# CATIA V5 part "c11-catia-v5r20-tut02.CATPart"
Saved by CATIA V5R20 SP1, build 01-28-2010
Part number: c11tut2
Bounding box of the stored display mesh (mm): x -175 to 0, y -36.667 to 105, z 0 to 36.632
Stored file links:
  D:\v5_r20\psrt_files_downloaded\c11\c11-catia-v5r20-tut02.CATPart
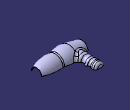
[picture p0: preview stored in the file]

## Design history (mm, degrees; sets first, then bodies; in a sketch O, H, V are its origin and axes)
Body1 (main body)
  Plane1: type Offset, RefPlane yz-plane, Offset 75, reversed
  Plane2: type Offset, RefPlane yz-plane, Offset 125, reversed
  Plane3: type Offset, RefPlane yz-plane, Offset 175, reversed
  Sketch1 on yz-plane, origin (0, 0, 0), H (0, 1, 0), V (0, 0, 1)
    arc A1 centre (0, 0) radius 20 from (20, 0) to (-20, 0) ccw
    point P1 (-20, 0)
    point P2 (20, 0)
    radius A1 = 20
    coincidence: P1 H, P2 H
  Sketch2 on Plane1, origin (-75, 0, 0), H (0, 1, 0), V (0, 0, 1)
    arc A1 centre (0, 0) radius 30 from (30, 0) to (-30, 0) ccw
    point P1 (-30, 0)
    point P2 (30, 0)
    radius A1 = 30
    coincidence: P1 H, P2 H
  Sketch3 on Plane2, origin (-125, 0, 0), H (0, 1, 0), V (0, 0, 1)
    arc A1 centre (0, 0) radius 35 from (35, 0) to (-35, 0) ccw
    point P1 (-35, 0)
    point P2 (35, 0)
    radius A1 = 35
    coincidence: P1 H, P2 H
  Sketch4 on Plane3, origin (-175, 0, 0), H (0, 1, 0), V (0, 0, 1)
    arc A1 centre (0, 0) radius 25 from (25, 0) to (-25, 0) ccw
    point P1 (-25, 0)
    point P2 (25, 0)
    radius A1 = 25
    coincidence: P1 H, P2 H
  Sketch5 on xy-plane, origin (0, 0, 0), H (1, 0, 0), V (0, 1, 0)
    arc A1 centre (-53.2457, -93.0924) radius 125 from (0, 20) to (-75, 30) ccw
    point P2 (0, 20)
    point P3 (-75, 30)
    reference projected point E1 (0, 20) from Sketch1.P2
    reference projected point E2 (-75, 30) from Sketch2.P2
    line L1 (-175, 25) -> (-125, 35)
    point P4 (-175, 25)
    point P5 (-125, 35)
    reference projected point E3 (-125, 35) from Sketch3.P2
    reference projected point E4 (-175, 25) from Sketch4.P2
    arc A2 centre (-108.1667, -49.1667) radius 85.8335 from (-75, 30) to (-125, 35) ccw
    radius A1 = 125
    coincidence: P2 V, P2 E1, P3 E2, P5 E3, E4 P4
    tangency: A2 L1
  Sketch6 on xy-plane, origin (0, 0, 0), H (1, 0, 0), V (0, 1, 0)
    reference projected line E1 (-125, 35) -> (-175, 25) from Sketch5.L1
    point P1 (-125, 35)
    point P2 (-175, 25)
    reference projected arc E2 centre (-108.1667, -49.1667) radius 85.8335 from (-75, 30) to (-125, 35) ccw from Sketch5.A2
    point P3 (-75, 30)
    point P4 (-125, 35)
    reference projected arc E3 centre (-53.2457, -93.0924) radius 125 from (0, 20) to (-75, 30) ccw from Sketch5.A1
    point P5 (0, 20)
    point P6 (-75, 30)
    point P7 (-75, -30)
    point P8 (0, -20)
    point P9 (-125, -35)
    point P10 (-75, -30)
    point P11 (-175, -25)
    point P12 (-125, -35)
    arc A1 centre (-53.2457, 93.0924) radius 125 from (0, -20) to (-75, -30) cw
    arc A2 centre (-108.1667, 49.1667) radius 85.8335 from (-75, -30) to (-125, -35) cw
    line L1 (-125, -35) -> (-175, -25)
    symmetry: P6 P7 H, P5 P8 H, E3 A1 H, P4 P9 H, P3 P10 H, E2 A2 H, P2 P11 H, P1 P12 H, E1 L1 H
  Loft1: Sections (Sketch1; Sketch2; Sketch3; Sketch4), Guides (Sketch5; Sketch6)
  Sketch7 on xy-plane, origin (0, 0, 0), H (1, 0, 0), V (0, 1, 0)
    line L1 (-160, 10) -> (-160, 105)
    point P1 (-160, 10)
    point P2 (-160, 105)
    reference projected line E1 (-175, -25) -> (-175, 25) from edge of Loft1
    reference projected point E2 (-175, 25) from vertex [face of Loft1]
    distance P1 E1 = 15
    distance E2 P1 V = 15
    distance H P2 = 105
    vertical: L1 V
  Sketch8 on xy-plane, origin (0, 0, 0), H (1, 0, 0), V (0, 1, 0)
    point P1 (-125, 105)
    construction line L1 (-125, 105) -> (-110.3491, 0.7536)
    line L2 (-125, 105) -> (-123.011, 90.8478)
    point P3 (-123.011, 90.8478)
    arc A1 centre (-129.9429, 89.8736) radius 7 from (-125.3895, 84.5571) to (-123.011, 90.8478) ccw
    point P5 (-123.011, 90.8478)
    arc A2 centre (-121.4865, 80) radius 6 from (-125.3895, 84.5571) to (-123.3627, 74.3009) ccw
    point P7 (-121.4865, 80)
    arc A3 centre (-124.8481, 69.7891) radius 4.75 from (-122.6028, 65.6033) to (-123.3627, 74.3009) ccw
    arc A4 centre (-118.3485, 57.6723) radius 9 from (-122.6028, 65.6033) to (-122.4134, 49.6426) ccw
    point P11 (-118.3485, 57.6723)
    arc A5 centre (-127.8333, 38.9362) radius 12 from (-115.9501, 40.6063) to (-122.4134, 49.6426) ccw
    construction line L3 (-160, 10) -> (-111.6486, 10)
    point P15 (-160, 10)
    line L4 (-111.6486, 10) -> (-115.9501, 40.6063)
    reference projected point E1 (-160, 10) from Sketch7.P1
    construction line L5 (-160, 105) -> (-125, 105)
    point P17 (-160, 105)
    point P18 (-125, 105)
    reference projected point E2 (-160, 105) from Sketch7.P2
    radius A1 = 7
    radius A2 = 6
    radius A3 = 4.75
    radius A4 = 9
    radius A5 = 12
    length L5 = 35
    distance P7 L5 = 25
    angle L5 L1 = 98
    parallelism: L2 L1
    tangency: A1 L1, A2 A1, A2 A3, A3 L1, A4 A3, A5 A4, L4 A5
    coincidence: P5 L1, P5 P3, P7 L1, P11 L1, P15 E1, P17 E2, P1 P18, L1 L4
    horizontal: L3 H, L5 H
  Plane4: type Offset, RefPlane zx-plane, Offset 105
  Sketch9 on Plane4, origin (0, 105, 0), H (-1, 0, 0), V (0, 0, 1)
    arc A1 centre (142.5, 0) radius 17.5 from (160, 0) to (125, 0) ccw
    point P2 (160, 0)
    point P3 (125, 0)
    reference projected point E1 (125, 0) from Sketch8.P1
    reference projected point E2 (160, 0) from Sketch7.P2
    radius A1 = 17.5
    coincidence: P3 E1, P2 E2
  Sweep1: type Unspec, Profile Sketch9, Guide (Sketch7; Sketch8), FittingPoints (Sketch7.P2; Sketch8.P1)
  Trim1: Trimmed (Sweep1; Loft1)
  Line1: type PtPt, FirstPoint vertex [face of Loft1], SecondPoint vertex [face of Loft1]
  Fill1: Boundary (edge of Loft1; Line1)
  Line2: type PtPt, FirstPoint vertex [face of Sweep1], SecondPoint vertex [face of Sweep1]
  Fill2: Boundary (edge of Sweep1; Line2)
  Line3: type PtPt, FirstPoint vertex [face of Loft1], SecondPoint vertex [face of Loft1]
  Fill3: Boundary (Line3; edge of Loft1)
  Fill4: Boundary (edge of Sweep1; edge of Sweep1; edge of Sweep1; edge of Sweep1; edge of Sweep1; edge of Sweep1; edge of Sweep1; Line2; edge of Sweep1; edge of Loft1; Line3; edge of Loft1; edge of Loft1; edge of Loft1; Line1; edge of Loft1; edge of Loft1)
  Join1: Elements (Fill4; Fill3; Trim1; Fill1; Fill2)
  CloseSurface1: CloseElement Join1
  Fillet1: radius 8, on edge [face of CloseSurface1 | face of CloseSurface1]
  Fillet2: radius 12, on edge [face of CloseSurface1 | face of CloseSurface1] (x2)
  Shell1: IntOffset 1, Face (face of CloseSurface1; face of CloseSurface1; face of CloseSurface1), ExtOffset 0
